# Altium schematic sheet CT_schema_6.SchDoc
size 295 x 165 mm
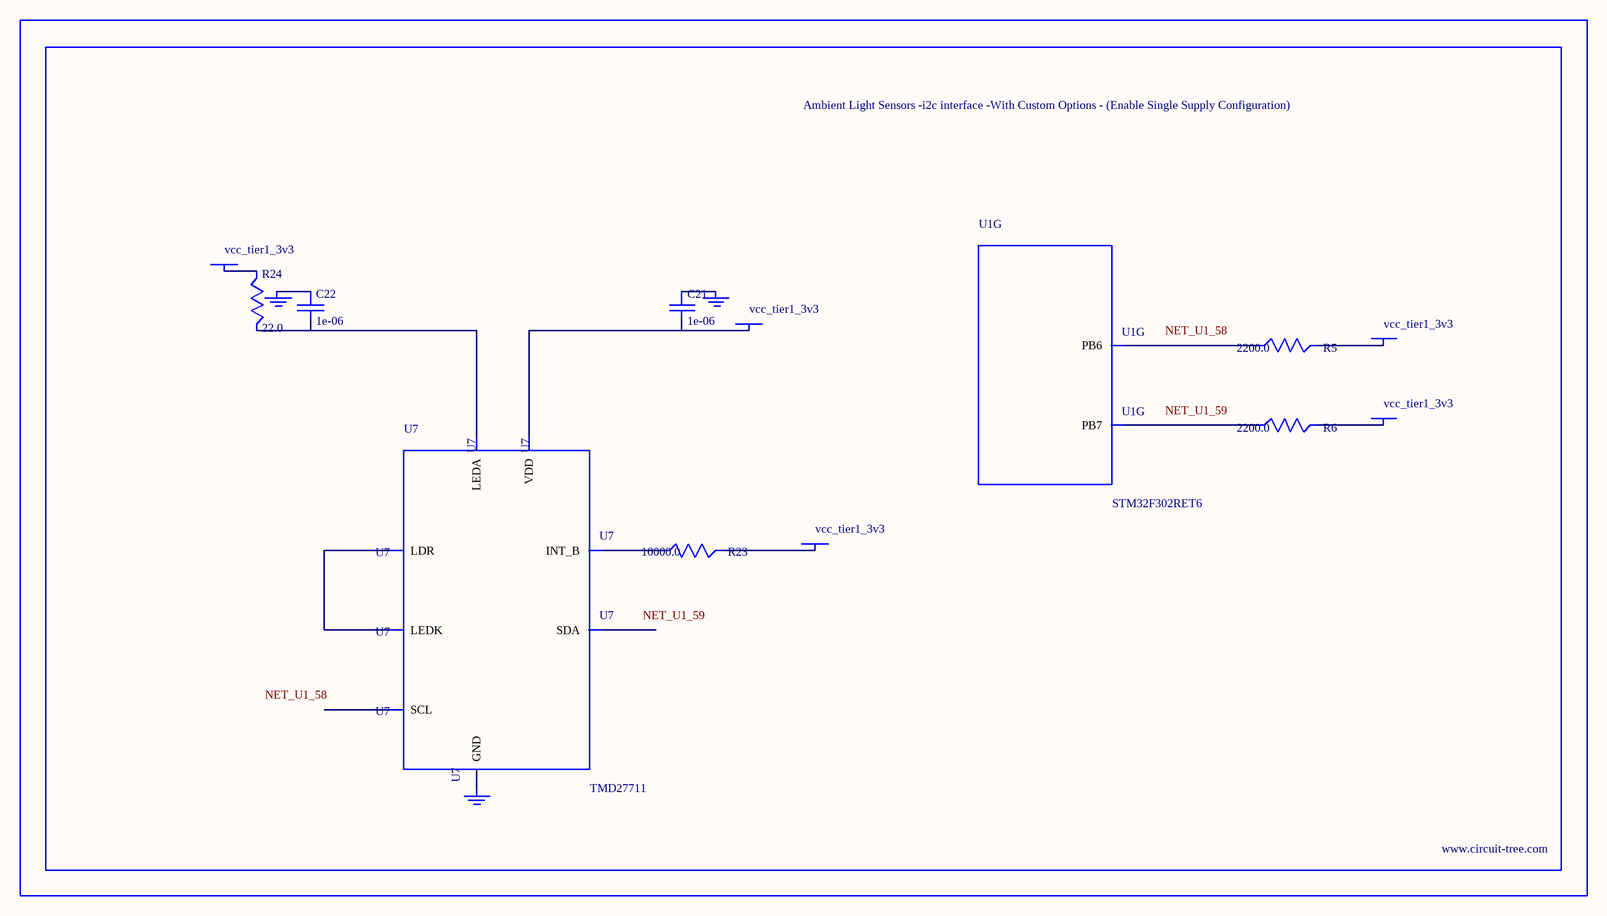
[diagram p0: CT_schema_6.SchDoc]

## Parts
BORDER5  (no value)
C21  1e-06  [C0603]
C22  1e-06  [C0603]
GND_INSTANCE_5_0  (no value)
GND_INSTANCE_5_1  (no value)
GND_INSTANCE_5_2  (no value)
POWER_INSTANCE_5_0  vcc_tier1_3v3
POWER_INSTANCE_5_1  vcc_tier1_3v3
POWER_INSTANCE_5_2  vcc_tier1_3v3
POWER_INSTANCE_5_3  vcc_tier1_3v3
POWER_INSTANCE_5_4  vcc_tier1_3v3
R5  2200.0  [R0603]
R6  2200.0  [R0603]
R23  10000.0  [R0603]
R24  22.0  [R0603]
U1  STM32F302RET6  [LQFP64]  (part G of 7)
U7  TMD27711  [SMD-8]

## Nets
NetC21_1: C21.1 GND_INSTANCE_5_0.0(GND)
NetC21_2: C21.2 POWER_INSTANCE_5_0.0(PWR) U7.1(VDD)
NetC22_1: C22.1 GND_INSTANCE_5_1.0(GND)
NetC22_2: C22.2 R24.2 U7.4(LEDA)
NetGND_INSTANCE_5_2_0: GND_INSTANCE_5_2.0(GND) U7.3(GND)
NetPOWER_INSTANCE_5_1_0: POWER_INSTANCE_5_1.0(PWR) R24.1
NetPOWER_INSTANCE_5_2_0: POWER_INSTANCE_5_2.0(PWR) R23.2
NetPOWER_INSTANCE_5_3_0: POWER_INSTANCE_5_3.0(PWR) R5.2
NetPOWER_INSTANCE_5_4_0: POWER_INSTANCE_5_4.0(PWR) R6.2
NetR5_1: R5.1 U1.58(PB6)
NetR6_1: R6.1 U1.59(PB7)
NetR23_1: R23.1 U7.7(INT_B)
NetU7_5: U7.5(LEDK) U7.6(LDR)

Not connected (* = marked no-connect by the designer): U7 2(SCL) 8(SDA)

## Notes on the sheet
- Labels drawn without touching a wire or pin: NET_U1_58, NET_U1_59

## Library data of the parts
BORDER5 = BORDER_PAGE5
C21 C22 = C0603C105K3RACTU
GND_INSTANCE_5_0-GND_INSTANCE_5_2 = GND
POWER_INSTANCE_5_0-POWER_INSTANCE_5_4 = PWR
R5 R6 = RC0603JR-072K2L
R23 = RC0603JR-0710KL
R24 = RC0603JR-0722RL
